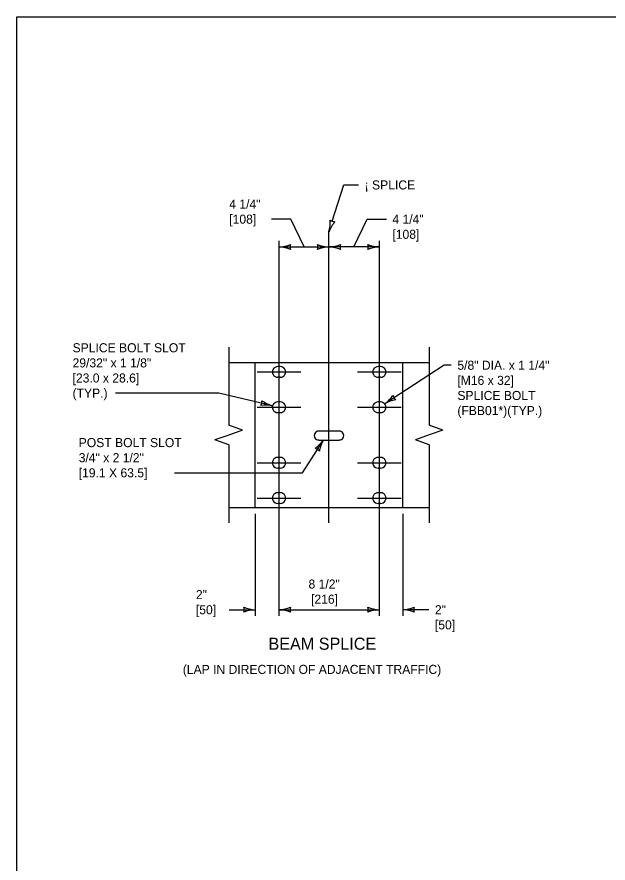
# Model space of a CAD drawing. Extents: x 49991.4 to 50021, y 49987.6 to 50011.4.
# Drawn here: x 49999.38 to 50003.3, y 49993.4 to 49999 of the extents above; entities that cross this region are included whole.
import ezdxf

# ---------------------------------------------------------------- set-up
doc = ezdxf.new("R2010")
doc.units = 0
for name, color, linetype in [('Level 1', 7, 'Continuous'), ('Level 2', 7, 'Continuous'), ('Level 3', 7, 'Continuous'), ('Level 4', 7, 'Continuous'), ('Level 5', 7, 'Continuous'), ('Level 6', 7, 'Continuous')]:
    doc.layers.add(name, color=color, linetype=linetype)

msp = doc.modelspace()

# ---------------------------------------------------------------- linework, layer by layer
at = {"layer": 'Level 1'}
for p, q in [((50000.7867, 49996.7126), (50002.1136, 49996.7126)), ((50000.9618, 49995.7513), (50000.9618, 49996.7126)), ((50001.128, 49996.6847), (50001.1109, 49996.6847)), ((50001.7924, 49996.6848), (50001.7753, 49996.6848)), ((50001.128, 49996.6139), (50001.1109, 49996.6139)), ((50001.7924, 49996.614), (50001.7753, 49996.614)), ((50001.1279, 49996.4508), (50001.1108, 49996.4508)), ((50001.7924, 49996.4508), (50001.7753, 49996.4508)), ((50001.1279, 49996.38), (50001.1108, 49996.38)), ((50001.7924, 49996.38), (50001.7753, 49996.38)), ((50001.5187, 49996.2577), (50001.382, 49996.2577)), ((50001.382, 49996.1991), (50001.5187, 49996.1991)), ((50001.1279, 49996.0839), (50001.1108, 49996.0839)), ((50001.7924, 49996.0839), (50001.7753, 49996.0839)), ((50001.1279, 49996.0131), (50001.1108, 49996.0131)), ((50001.7924, 49996.0131), (50001.7753, 49996.0131)), ((50001.1279, 49995.85), (50001.1108, 49995.85)), ((50001.7924, 49995.85), (50001.7753, 49995.85)), ((50000.7867, 49995.7513), (50002.1136, 49995.7513)), ((50001.1279, 49995.7792), (50001.1108, 49995.7792)), ((50001.7924, 49995.7792), (50001.7753, 49995.7792))]:
    msp.add_line(p, q, dxfattribs=at)
msp.add_lwpolyline([(49999.3835, 49998.9992), (50016.7501, 49998.9992), (50016.7501, 49987.7988), (49999.3835, 49987.7988)], close=True, dxfattribs=at)
for centre, major_axis, ratio, start_param, end_param in [((50001.1109, 49996.6493), (0.0354, 0), 0.998676, 1.570796, 4.712389), ((50001.128, 49996.6493), (0.0354, 0), 0.998676, 4.712389, 7.853982), ((50001.7753, 49996.6494), (0.0354, 0), 0.998676, 1.570796, 4.712389), ((50001.7924, 49996.6494), (0.0354, 0), 0.998676, 4.712389, 7.853982), ((50001.1108, 49996.4154), (0.0354, 0), 0.998676, 1.570796, 4.712389), ((50001.1279, 49996.4154), (0.0354, 0), 0.998676, 4.712389, 7.853982), ((50001.7753, 49996.4154), (0.0354, 0), 0.998676, 1.570796, 4.712389), ((50001.7924, 49996.4154), (0.0354, 0), 0.998676, 4.712389, 7.853982), ((50001.382, 49996.2284), (0.0296, 0), 0.988923, 1.570796, 4.712389), ((50001.5187, 49996.2284), (0.0294, 0), 0.995211, 4.712389, 7.853982), ((50001.1108, 49996.0485), (0.0354, 0), 0.998676, 1.570796, 4.712389), ((50001.1279, 49996.0485), (0.0354, 0), 0.998676, 4.712389, 7.853982), ((50001.7753, 49996.0485), (0.0354, 0), 0.998676, 1.570796, 4.712389), ((50001.7924, 49996.0485), (0.0354, 0), 0.998676, 4.712389, 7.853982), ((50001.1108, 49995.8146), (0.0354, 0), 0.998676, 1.570796, 4.712389), ((50001.1279, 49995.8146), (0.0354, 0), 0.998676, 4.712389, 7.853982), ((50001.7753, 49995.8146), (0.0354, 0), 0.998676, 1.570796, 4.712389), ((50001.7924, 49995.8146), (0.0354, 0), 0.998676, 4.712389, 7.853982)]:
    msp.add_ellipse(centre, major_axis=major_axis, ratio=ratio, start_param=start_param, end_param=end_param, dxfattribs=at)
at = {"layer": 'Level 3'}
for p, q in [((50001.4724, 49997.6466), (50001.5481, 49997.8872)), ((50001.5481, 49997.8872), (50001.6464, 49997.8872)), ((50001.1194, 49997.4766), (50001.4503, 49997.4766)), ((50001.7838, 49997.4766), (50001.4503, 49997.4766)), ((50002.2126, 49996.6938), (50001.8193, 49996.4384)), ((50002.2605, 49996.6938), (50002.2126, 49996.6938)), ((50000.7213, 49996.5095), (50000.0358, 49996.5095)), ((50001.0768, 49996.4255), (50000.7213, 49996.5095)), ((50001.2742, 49995.9819), (50001.4134, 49996.1991)), ((50000.4264, 49995.9819), (50001.2742, 49995.9819)), ((50000.9618, 49995.7113), (50000.9618, 49995.0357)), ((50001.9385, 49995.7113), (50001.9385, 49995.0357)), ((50000.7884, 49995.0757), (50000.9618, 49995.0757)), ((50001.1194, 49995.0757), (50001.7838, 49995.0757)), ((50002.1119, 49995.0757), (50001.9385, 49995.0757))]:
    msp.add_line(p, q, dxfattribs=at)
for points in [[(50001.2849, 49997.4766), (50001.1982, 49997.6606), (50001.0704, 49997.6606)], [(50001.6158, 49997.4766), (50001.7025, 49997.6606), (50001.8303, 49997.6606)]]:
    msp.add_lwpolyline(points, dxfattribs=at)
for centre, radius, start, end in [((50001.2249, 49997.6355), 0.233, 345.3497, 4.5995), ((50001.6595, 49997.5012), 0.2223, 139.9784, 160.1619), ((50001.4888, 49997.6989), 0.0548, 234.6612, 270.3836), ((50001.1079, 49997.7093), 0.233, 272.8273, 292.0772), ((50001.1103, 49997.2545), 0.2223, 67.456, 87.6395), ((50001.2477, 49997.4766), 0.0548, 162.1388, 197.8612), ((50001.4595, 49997.6987), 0.2223, 247.456, 267.6395), ((50001.3221, 49997.4766), 0.0548, 342.1388, 17.8612), ((50001.4618, 49997.2439), 0.233, 92.8273, 112.0772), ((50001.4388, 49997.7093), 0.233, 272.8273, 292.0772), ((50001.4412, 49997.2545), 0.2223, 67.456, 87.6395), ((50001.5786, 49997.4766), 0.0548, 162.1388, 197.8612), ((50001.793, 49997.6987), 0.2223, 247.456, 267.6395), ((50001.6556, 49997.4766), 0.0548, 342.1388, 17.8612), ((50001.7953, 49997.2439), 0.233, 92.8273, 112.0772), ((50000.952, 49996.455), 0.0548, 328.8398, 4.5621), ((50001.1368, 49996.6395), 0.2223, 234.1569, 254.3405), ((50001.6826, 49996.6271), 0.233, 305.9216, 325.1715), ((50001.9329, 49996.2473), 0.2223, 100.5503, 120.7338), ((50001.9267, 49996.5084), 0.0548, 195.2331, 230.9555), ((50001.0345, 49996.1964), 0.233, 79.5282, 98.7781), ((50001.2313, 49996.3266), 0.2223, 304.8128, 324.9963), ((50001.6155, 49996.0833), 0.233, 150.1841, 169.434), ((50001.3442, 49996.0911), 0.0548, 39.4956, 75.218), ((50000.971, 49995.2978), 0.2223, 247.456, 267.6395), ((50000.8336, 49995.0757), 0.0548, 342.1388, 17.8612), ((50000.9733, 49994.843), 0.233, 92.8273, 112.0772), ((50001.1079, 49995.3084), 0.233, 272.8273, 292.0772), ((50001.1103, 49994.8536), 0.2223, 67.456, 87.6395), ((50001.2477, 49995.0757), 0.0548, 162.1388, 197.8612), ((50001.793, 49995.2979), 0.2223, 247.456, 267.6395), ((50001.6556, 49995.0757), 0.0548, 342.1388, 17.8612), ((50001.7953, 49994.843), 0.233, 92.8273, 112.0772), ((50001.927, 49995.3084), 0.233, 272.8273, 292.0772), ((50001.9294, 49994.8536), 0.2223, 67.456, 87.6395), ((50002.0668, 49995.0757), 0.0548, 162.1388, 197.8612)]:
    msp.add_arc(centre, radius, start, end, dxfattribs=at)
at = {"layer": 'Level 4'}
msp.add_line((50001.9385, 49995.7513), (50001.9385, 49996.7126), dxfattribs=at)
at = {"layer": 'Level 5'}
for p, q in [((50001.4503, 49995.6513), (50001.4503, 49997.5766)), ((50001.1194, 49995.0357), (50001.1194, 49997.5166)), ((50001.7838, 49995.0357), (50001.7838, 49997.5166)), ((50000.9755, 49996.6494), (50001.2634, 49996.6494)), ((50001.6399, 49996.6494), (50001.9278, 49996.6494)), ((50000.9754, 49996.4154), (50001.2633, 49996.4154)), ((50001.6399, 49996.4154), (50001.9278, 49996.4154)), ((50000.9754, 49996.0485), (50001.2633, 49996.0485)), ((50001.6399, 49996.0485), (50001.9278, 49996.0485)), ((50000.9754, 49995.8146), (50001.2633, 49995.8146)), ((50001.6399, 49995.8146), (50001.9278, 49995.8146))]:
    msp.add_line(p, q, dxfattribs=at)
at = {"layer": 'Level 6'}
for p, q in [((50000.7867, 49996.8126), (50000.7867, 49996.2968)), ((50002.1136, 49996.8126), (50002.1136, 49996.297)), ((50000.8781, 49996.2644), (50000.7867, 49996.2968)), ((50002.205, 49996.2646), (50002.1136, 49996.297)), ((50000.8781, 49996.2644), (50000.7867, 49996.232)), ((50002.205, 49996.2646), (50002.1136, 49996.2322)), ((50000.7867, 49996.232), (50000.6953, 49996.1996)), ((50000.7867, 49996.1672), (50000.6953, 49996.1996)), ((50002.1136, 49996.2322), (50002.0222, 49996.1998)), ((50002.1136, 49996.1674), (50002.0222, 49996.1998)), ((50000.7867, 49996.1672), (50000.7867, 49995.6513)), ((50002.1136, 49996.1674), (50002.1136, 49995.6513))]:
    msp.add_line(p, q, dxfattribs=at)

# ---------------------------------------------------------------- texts
at = {"layer": 'Level 2'}
for s, height, p in [('¡ SPLICE', 0.06, (50001.6864, 49997.8572)), ('4 1/4"', 0.06, (50000.7899, 49997.7306)), ('[108]', 0.06, (50000.7899, 49997.6306)), ('4 1/4"', 0.06, (50001.8703, 49997.6306)), ('[108]', 0.06, (50001.8703, 49997.5306)), ('SPLICE BOLT SLOT', 0.06, (49999.7521, 49996.7795)), ('29/32" x 1 1/8"', 0.06, (49999.7521, 49996.6795)), ('5/8" DIA. x 1 1/4"', 0.06, (50002.3006, 49996.6638)), ('[23.0 x 28.6]', 0.06, (49999.7521, 49996.5795)), ('[M16 x 32]', 0.06, (50002.3006, 49996.5638)), ('(TYP.)', 0.06, (49999.7521, 49996.4795)), ('SPLICE BOLT ', 0.06, (50002.3006, 49996.4638)), ('(FBB01*)(TYP.) ', 0.06, (50002.3006, 49996.3638)), ('POST BOLT SLOT', 0.06, (49999.7927, 49996.1519)), ('3/4" x 2 1/2"', 0.06, (49999.7927, 49996.0519)), ('[19.1 X 63.5]', 0.06, (49999.7927, 49995.9519)), ('8 1/2"', 0.06, (50001.3146, 49995.2157)), ('2"', 0.06, (50000.5689, 49995.1457)), ('[216]', 0.06, (50001.3314, 49995.1157)), ('[50]', 0.06, (50000.5689, 49995.0457)), ('2"', 0.06, (50002.1519, 49995.0457)), ('[50]', 0.06, (50002.1519, 49994.9457)), ('BEAM SPLICE', 0.08, (50001.0495, 49994.8109)), ('(LAP IN DIRECTION OF ADJACENT TRAFFIC)', 0.06, (50000.4821, 49994.6509))]:
    msp.add_text(s, height=height, dxfattribs=at).set_placement(p)

doc.saveas('drawing.dxf')
